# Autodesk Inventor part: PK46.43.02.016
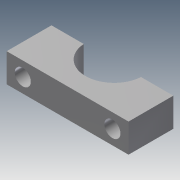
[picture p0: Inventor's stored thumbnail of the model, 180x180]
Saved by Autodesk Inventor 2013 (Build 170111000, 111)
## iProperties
Shininess: 64.0
Length Units: 11269
Angle Units: 11279
Time Units: 11290
Mass Units: 11283
Length Display Precision: 3
Angle Display Precision: 2
Compacted: True
Part Number: PK46.43.02.016
Document SubType Name: Modeling
Created: 2004-12
Material: Steel, High Strength Low Alloy
Designer: ELarisa
Manufacturer: Standard
Standards Organization: Custom
Density: 7.84 g/cm^3
Density: 0.0
Volumn: 0.0
Area: 0.0
PropertySet Name: Model Information
Control State: 0
Master: False
Checked Out: False
Checked Out Date: 2008-10-09
Last Check In Date: 2008-10-09
Author: ELarisa
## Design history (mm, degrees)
sketch "Эскиз1"
  geometry: L1 (-23.935, -9.108)-(-23.935, 15.892); L2 (44.065, 15.892)-(44.065, -9.108); L3 (44.065, -9.108)-(-23.935, -9.108); L4 (-23.935, 15.892)-(-5.904, 15.892); L5 (26.034, 15.892)-(44.065, 15.892); A1 r 16 centre (10.065, 16.892) between (-5.904, 15.892) and (26.034, 15.892)
  constraints: 10 end point, 3 parallel, 2 perpendicular, 2 point on circle, 1 centre point, 1 vertical
  dimensions: "d0" = 68 distance of L2.end L1.start; "d2" = 25 distance of L1.start L1.end; "d3" = 34 distance from line of L1 A1.centre; "d4" = 32 diameter of A1; "d5" = 1 distance from line of A1.centre L4; "d6" = 25 distance of L2.start L2.end
extrude "Выдавливание1" new body sketch "Эскиз1" distance "d7" = 16; taper "d8" = 0 deg
sketch "Эскиз2"
  geometry: L1 (0, -16)-(18.031, -16) reference; L2 (0, 0)-(0, -16) reference; L3 (49.969, -16)-(68, -16) reference; L4 (68, 0)-(68, -16) reference; L5 (49.969, 0)-(68, 0) reference; L6 (49.969, 0)-(49.969, -16) reference; 2 further points
  dimensions: "d9" = 50 distance of point (59, -8) point (9, -8); "d10" = 8 distance from line of L1 point (9, -8); "d11" = 8 distance from line of point (59, -8) L3; "d12" = 9 distance from line of point (9, -8) L2
hole "Отверстие1" sketch "Эскиз2" diameter "d13" = 9; stored, may be unused: countersink angle "d17" = 82 deg, drill point angle "d19" = 118 deg; dims "d14" = 6, "d15" = 4, "d16" = 2, "d18" = 8
body "Solid1"
node "Спроецированная петля1"
other parameters: "d1" = 1
